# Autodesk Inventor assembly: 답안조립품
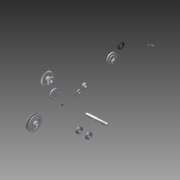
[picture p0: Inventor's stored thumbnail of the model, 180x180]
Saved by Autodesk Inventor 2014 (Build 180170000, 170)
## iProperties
Created: 2016-01
Part Number: 답안조립품
Document SubType Name: Assembly
Designer: SCD-A13
Author: SCD-A13
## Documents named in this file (16)
- C:\Users\SCD-A13\Desktop\460105V1034\답안조립품.iam
- C:\Users\SCD-A13\Desktop\460105V1034\1.본체.ipt
- C:\Users\SCD-A13\Desktop\460105V1034\V-벨트풀리.ipt
- C:\Users\SCD-A13\Desktop\460105V1034\뒤커버.ipt
- C:\Users\SCD-A13\Desktop\460105V1034\멈춤나사 - M4x10.ipt
- C:\Users\SCD-A13\Desktop\460105V1034\베어링 6203.ipt
- C:\Users\SCD-A13\Desktop\460105V1034\볼트 M3 x 8.ipt
- C:\Users\SCD-A13\Desktop\460105V1034\볼트 M3 x 10.ipt
- C:\Users\SCD-A13\Desktop\460105V1034\부시1.ipt
- C:\Users\SCD-A13\Desktop\460105V1034\부시2.ipt
- C:\Users\SCD-A13\Desktop\460105V1034\스퍼기어.ipt
- C:\Users\SCD-A13\Desktop\460105V1034\앞커버.ipt
- C:\Users\SCD-A13\Desktop\460105V1034\오일씰 28 40 8.ipt
- C:\Users\SCD-A13\Desktop\460105V1034\축.ipt
- C:\Users\SCD-A13\Desktop\460105V1034\키 - 5 x 5 x 18.ipt
- C:\Users\SCD-A13\Desktop\460105V1034\키 - 6 x 6 x 22.ipt
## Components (4 placed, 4 different names)
1. 1.본체:1
2. V-벨트풀리:1
3. ISO 4762 M3 x 8:1
4. ISO 4762 M3 x 10:1
